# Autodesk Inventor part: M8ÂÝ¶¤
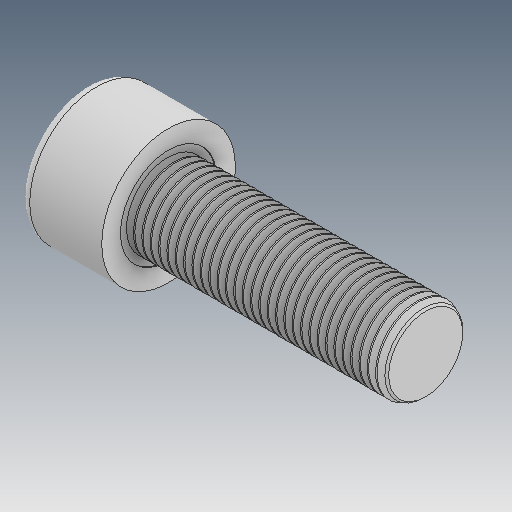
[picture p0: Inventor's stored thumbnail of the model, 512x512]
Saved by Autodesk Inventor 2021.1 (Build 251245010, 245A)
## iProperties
Created: 2014-12
Part Number: M8ÂÝ¶¤
Material: Ogólny
Document SubType Name: Modeling
Designer: user
Density: 1 g/cm^3
Appearance: Domyślna
Author: user
Revision Number: ÈÎºÎ
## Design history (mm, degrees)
feature "Ô²½Ç1"
node "Bryła1"
